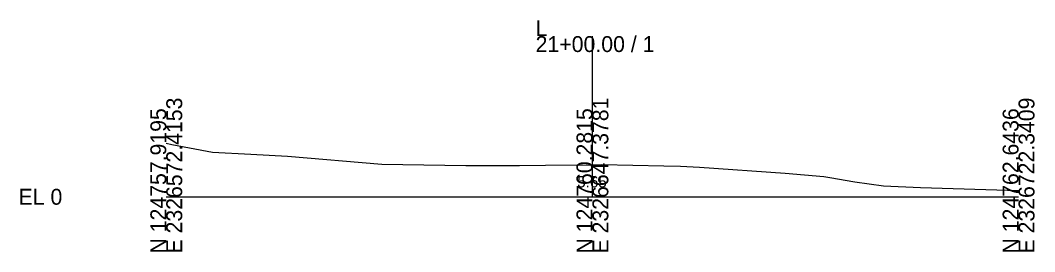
# Model space of a CAD drawing. Extents: x -26 to 1153, y -10 to 9525.
# Drawn here: x 974.3 to 1152.8, y 2990.3 to 3031.1 of the extents above; entities that cross this region are included whole.
import ezdxf

# ---------------------------------------------------------------- set-up
doc = ezdxf.new("R2010")
doc.units = 0
for name, color, linetype in [('Exist Cross Section Cell', 7, 'Continuous'), ('Exist XS Center Line Elevation Label', 7, 'Continuous'), ('Exist XS Ground Line', 7, 'Continuous')]:
    doc.layers.add(name, color=color, linetype=linetype)

msp = doc.modelspace()

# ---------------------------------------------------------------- linework, layer by layer
at = {"layer": 'Exist Cross Section Cell'}
for p, q in [((1075, 3000), (1075, 3028.32)), ((1000, 3000), (1075, 3000)), ((1075, 3000), (1150, 3000))]:
    msp.add_line(p, q, dxfattribs=at)
at = {"layer": 'Exist XS Ground Line'}
for p, q in [((1000, 3009.44), (1000.99, 3009.21)), ((1000.99, 3009.21), (1008.16, 3007.89)), ((1008.16, 3007.89), (1014.88, 3007.52)), ((1014.88, 3007.52), (1021.35, 3007.17)), ((1021.35, 3007.17), (1037.91, 3005.73)), ((1037.91, 3005.73), (1052.7, 3005.5)), ((1052.7, 3005.5), (1057.89, 3005.5)), ((1057.89, 3005.5), (1062.19, 3005.5)), ((1062.19, 3005.5), (1066.77, 3005.55)), ((1066.77, 3005.55), (1075, 3005.65)), ((1075, 3005.65), (1076.63, 3005.67)), ((1076.63, 3005.67), (1087.55, 3005.46)), ((1087.55, 3005.46), (1090.5, 3005.4)), ((1090.5, 3005.4), (1093.85, 3005.24)), ((1093.85, 3005.24), (1108.95, 3004.17)), ((1108.95, 3004.17), (1115.74, 3003.59)), ((1115.74, 3003.59), (1116.78, 3003.4)), ((1116.78, 3003.4), (1121.18, 3002.64)), ((1121.18, 3002.64), (1126.24, 3001.92)), ((1126.24, 3001.92), (1132.73, 3001.65)), ((1132.73, 3001.65), (1150, 3001.08))]:
    msp.add_line(p, q, dxfattribs=at)

# ---------------------------------------------------------------- texts
at = {"layer": 'Exist Cross Section Cell'}
for s, p in [('L', (1065, 3028.32)), ('21+00.00 / 1', (1065, 3025.52)), ('EL 0', (974, 2998.6))]:
    msp.add_text(s, height=2.8, dxfattribs=at).set_placement(p)
for s, p in [('E 2326572.4153', (1002.8, 2990)), ('E 2326647.3781', (1077.8, 2990)), ('E 2326722.3409', (1152.8, 2990)), ('N 124757.9195', (1000, 2990)), ('N 124760.2815', (1075, 2990)), ('N 124762.6436', (1150, 2990))]:
    msp.add_text(s, height=2.8, rotation=90, dxfattribs=at).set_placement(p)
at = {"layer": 'Exist XS Center Line Elevation Label'}
msp.add_text('5.65', height=2, dxfattribs=at).set_placement((1072.32, 3001.65))

doc.saveas('drawing.dxf')
